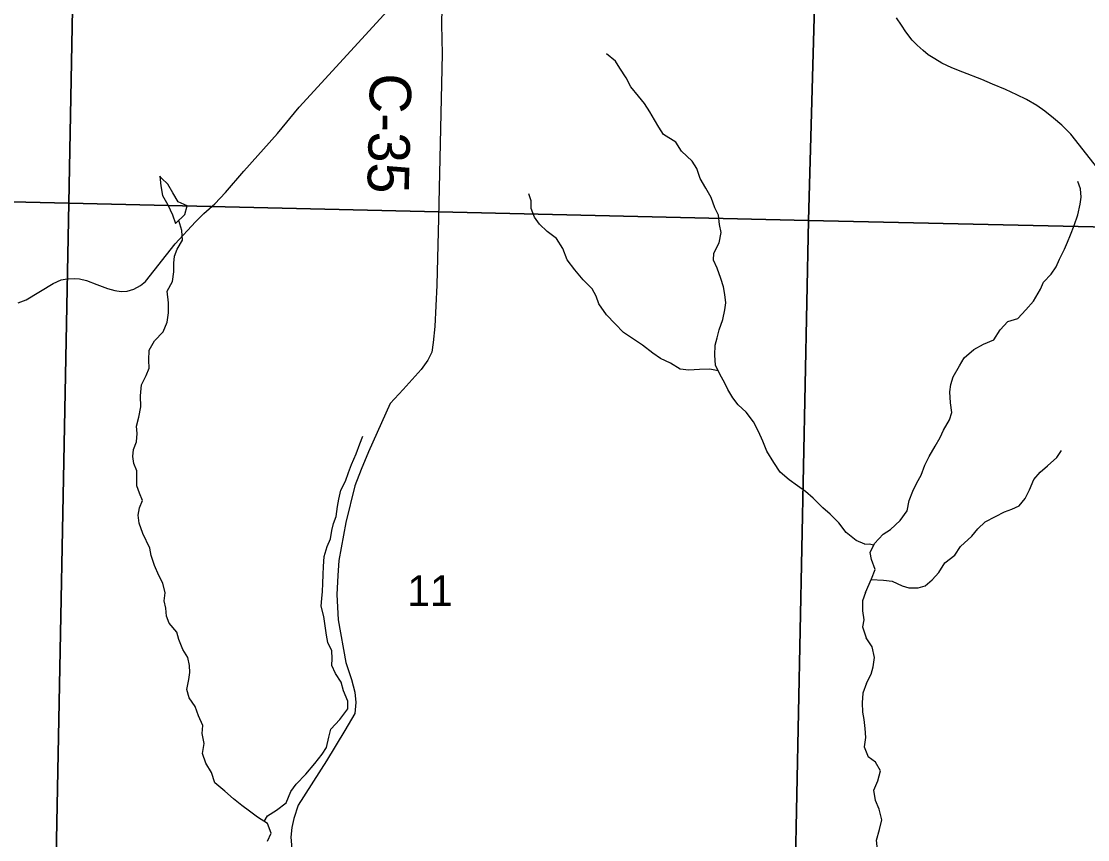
# Model space of a CAD drawing. Extents: x -3.6 to 34, y 0 to 32.8.
# Drawn here: x -1.871 to -0.41, y 27.165 to 28.286 of the extents above; entities that cross this region are included whole.
import ezdxf

# ---------------------------------------------------------------- set-up
doc = ezdxf.new("R2010")
doc.units = 0
for name, color, linetype in [('GM_X_Corporation', 7, 'Continuous'), ('GM_X_County_Road', 7, 'Continuous'), ('GM_X_County_Road_Text', 7, 'Continuous'), ('GM_X_Minor_Lake', 7, 'Continuous'), ('GM_X_Minor_River', 7, 'Continuous'), ('GM_X_Section_Text', 7, 'Continuous'), ('GM_X_State_Route', 7, 'Continuous')]:
    doc.layers.add(name, color=color, linetype=linetype)

msp = doc.modelspace()

# ---------------------------------------------------------------- linework, layer by layer
at = {"layer": 'GM_X_Corporation'}
for points in [[(-2.8121, 29.1143), (-1.8059, 29.1018), (-1.7854, 29.1006), (-1.8056, 28.0368), (-2.8264, 28.0607)], [(-1.7854, 29.1006), (-0.7893, 29.0771), (-0.7627, 29.0764), (-0.7925, 28.0131), (-1.8056, 28.0368)], [(-0.7627, 29.0764), (0.223, 29.0627), (0.2209, 28.9831), (0.2524, 28.9828), (0.2336, 27.9902), (-0.7925, 28.0131)], [(-1.8056, 28.0368), (-1.8251, 27.0226), (-2.8456, 27.0298), (-2.8264, 28.0607)], [(-0.7925, 28.0131), (-0.8131, 27.0015), (-1.8251, 27.0226), (-1.8056, 28.0368)], [(-0.7925, 28.0131), (0.2336, 27.9902), (0.2053, 26.9746), (-0.8131, 27.0015)]]:
    msp.add_lwpolyline(points, close=True, dxfattribs=at)
at = {"layer": 'GM_X_County_Road'}
msp.add_lwpolyline([(-1.2948, 28.3054), (-1.2951, 28.2819), (-1.2943, 28.2415), (-1.2993, 28.0164), (-1.3015, 27.9247), (-1.3043, 27.8681), (-1.3066, 27.8459), (-1.3084, 27.8327), (-1.3139, 27.8219), (-1.3231, 27.8089), (-1.3478, 27.7817), (-1.3654, 27.7625), (-1.395, 27.6961), (-1.4054, 27.672), (-1.4139, 27.6497), (-1.426, 27.5993), (-1.4356, 27.5472), (-1.4372, 27.5268), (-1.4386, 27.5005), (-1.4367, 27.4657), (-1.426, 27.4076), (-1.4184, 27.3841), (-1.4137, 27.3669), (-1.4125, 27.3524), (-1.4141, 27.3375), (-1.4278, 27.3143), (-1.4527, 27.2728), (-1.4914, 27.2119), (-1.4974, 27.1935), (-1.5, 27.1813), (-1.5014, 27.168), (-1.5002, 27.152)], dxfattribs=at)
at = {"layer": 'GM_X_Minor_Lake'}
for points in [[(-1.6786, 28.0714), (-1.6811, 28.0738), (-1.6798, 28.0606), (-1.6773, 28.0477), (-1.6698, 28.0346), (-1.6636, 28.021), (-1.6596, 28.009)], [(-1.6596, 28.009), (-1.6469, 28.0213), (-1.6437, 28.0335), (-1.6559, 28.0386), (-1.6633, 28.051), (-1.67, 28.063), (-1.6786, 28.0714)]]:
    msp.add_lwpolyline(points, dxfattribs=at)
at = {"layer": 'GM_X_Minor_River'}
for points in [[(-0.7155, 27.5697), (-0.7271, 27.5748), (-0.7409, 27.5856), (-0.7509, 27.5987), (-0.7629, 27.6106), (-0.7729, 27.6192), (-0.7863, 27.6326), (-0.7967, 27.6419), (-0.8074, 27.6497), (-0.8189, 27.6578), (-0.8312, 27.6682), (-0.8398, 27.6814), (-0.8495, 27.6971), (-0.855, 27.7107), (-0.8609, 27.7239), (-0.868, 27.7374), (-0.8777, 27.7505), (-0.8888, 27.7605), (-0.8962, 27.7703), (-0.9028, 27.7815), (-0.9075, 27.7913), (-0.9134, 27.8015), (-0.92, 27.815), (-0.921, 27.8286), (-0.9201, 27.8423), (-0.9176, 27.8522), (-0.9148, 27.8632), (-0.9097, 27.8777), (-0.9073, 27.8907), (-0.9059, 27.9002), (-0.9073, 27.9119), (-0.909, 27.9221), (-0.9126, 27.9338), (-0.9177, 27.9481), (-0.9228, 27.9587), (-0.9223, 27.9685), (-0.9149, 27.9827), (-0.9121, 27.9968), (-0.9142, 28.0077), (-0.9159, 28.0206), (-0.9207, 28.0304), (-0.9258, 28.0447), (-0.9332, 28.0574), (-0.9407, 28.071), (-0.9454, 28.0845), (-0.9517, 28.0947), (-0.9663, 28.1081), (-0.9741, 28.1208), (-0.9909, 28.1311), (-0.9975, 28.1413), (-1.0033, 28.151), (-1.0096, 28.1623), (-1.017, 28.1735), (-1.0255, 28.1836), (-1.0359, 28.1963), (-1.0422, 28.2087), (-1.0511, 28.2219), (-1.057, 28.2316), (-1.0692, 28.2416)], [(-0.7145, 27.5035), (-0.7062, 27.5223), (-0.7011, 27.5349), (-0.7062, 27.5485), (-0.7082, 27.5583), (-0.7023, 27.5706), (-0.6901, 27.5833), (-0.6803, 27.5899), (-0.6669, 27.6019), (-0.6572, 27.6153), (-0.6544, 27.6294), (-0.6497, 27.6424), (-0.6442, 27.6538), (-0.6383, 27.6642), (-0.6332, 27.6779), (-0.6273, 27.6898), (-0.6188, 27.7039), (-0.6122, 27.7158), (-0.6074, 27.7257), (-0.5993, 27.7399), (-0.5961, 27.7502), (-0.5978, 27.7631), (-0.5987, 27.7786), (-0.5974, 27.7885), (-0.5945, 27.7988), (-0.5857, 27.8141), (-0.5794, 27.8248), (-0.5659, 27.8364), (-0.5528, 27.8435), (-0.5385, 27.8497), (-0.53, 27.8632), (-0.5196, 27.8747), (-0.5057, 27.8787), (-0.4949, 27.8906), (-0.4844, 27.9026), (-0.4749, 27.919), (-0.4708, 27.9289), (-0.46, 27.9397), (-0.4534, 27.9497), (-0.4486, 27.9604), (-0.442, 27.9738), (-0.4376, 27.9837), (-0.4336, 27.9936), (-0.4285, 28.0062), (-0.4238, 28.0211), (-0.4202, 28.0356), (-0.4189, 28.0451), (-0.4198, 28.0568), (-0.4237, 28.0666)], [(-0.9163, 27.8074), (-0.9275, 27.8096), (-0.9419, 27.8089), (-0.9566, 27.8083), (-0.9684, 27.8096), (-0.9814, 27.8177), (-0.9951, 27.8243), (-1.0055, 27.8314), (-1.0197, 27.8425), (-1.0457, 27.8595), (-1.0572, 27.8714), (-1.0692, 27.8841), (-1.0797, 27.8991), (-1.0833, 27.9093), (-1.0887, 27.9194), (-1.1011, 27.9321), (-1.1126, 27.9456), (-1.1231, 27.9594), (-1.129, 27.9748), (-1.1376, 27.9884), (-1.1506, 27.998), (-1.161, 28.008), (-1.1676, 28.0178), (-1.1724, 28.0298), (-1.1722, 28.0401), (-1.1757, 28.0499)], [(-1.677, 27.5161), (-1.6824, 27.5266), (-1.6883, 27.5405), (-1.6927, 27.5541), (-1.6948, 27.5639), (-1.7042, 27.5842), (-1.7094, 27.5986), (-1.7107, 27.6092), (-1.709, 27.6194), (-1.7046, 27.6294), (-1.7089, 27.6395), (-1.7125, 27.6497), (-1.7123, 27.6603), (-1.7125, 27.6702), (-1.7164, 27.68), (-1.7181, 27.6898), (-1.7171, 27.6993), (-1.7128, 27.71), (-1.7118, 27.7214), (-1.7128, 27.7313), (-1.7099, 27.7438), (-1.7072, 27.7579), (-1.7074, 27.7727), (-1.7062, 27.7879), (-1.6996, 27.8009), (-1.6956, 27.8108), (-1.6961, 27.8218), (-1.6956, 27.8355), (-1.6882, 27.8481), (-1.6764, 27.8608), (-1.6709, 27.8738), (-1.6692, 27.8867), (-1.6691, 27.9004), (-1.6709, 27.9163), (-1.6635, 27.9297), (-1.6618, 27.943), (-1.6617, 27.9547), (-1.6607, 27.9642), (-1.6571, 27.9738), (-1.6497, 27.9864), (-1.6507, 27.9997), (-1.6551, 28.0133)], [(-1.5379, 27.1895), (-1.5335, 27.1972), (-1.5211, 27.205), (-1.508, 27.2151), (-1.5015, 27.2304), (-1.4944, 27.2407), (-1.481, 27.2542), (-1.4688, 27.2692), (-1.4588, 27.2816), (-1.4525, 27.2911), (-1.4497, 27.3049), (-1.4469, 27.3159), (-1.4346, 27.3294), (-1.4235, 27.344), (-1.4233, 27.3546), (-1.4292, 27.3686), (-1.4324, 27.3806), (-1.4402, 27.3923), (-1.4453, 27.4032), (-1.4451, 27.4131), (-1.4456, 27.4233), (-1.4507, 27.435), (-1.4528, 27.4448), (-1.4563, 27.4705), (-1.4599, 27.4845), (-1.4589, 27.4951), (-1.458, 27.5046), (-1.4578, 27.5156), (-1.4572, 27.5278), (-1.4567, 27.5388), (-1.4557, 27.5525), (-1.4518, 27.5666), (-1.4471, 27.5769), (-1.4454, 27.5883), (-1.4429, 27.5978), (-1.4393, 27.6074), (-1.4376, 27.6214), (-1.4359, 27.6313), (-1.4331, 27.6435), (-1.4268, 27.6561), (-1.4225, 27.668), (-1.4185, 27.679), (-1.4119, 27.6936), (-1.4069, 27.7073), (-1.4029, 27.7176)], [(-0.7066, 27.5213), (-0.6899, 27.5203), (-0.6777, 27.519), (-0.6644, 27.5127), (-0.6549, 27.5098), (-0.6424, 27.5096), (-0.6326, 27.5124), (-0.6229, 27.5205), (-0.614, 27.5309), (-0.6058, 27.544), (-0.592, 27.5544), (-0.5842, 27.5663), (-0.5689, 27.5806), (-0.5604, 27.5906), (-0.5503, 27.6002), (-0.5364, 27.6073), (-0.524, 27.6139), (-0.5142, 27.6175), (-0.5041, 27.6222), (-0.4959, 27.6322), (-0.49, 27.644), (-0.4838, 27.6582), (-0.4753, 27.6685), (-0.4652, 27.6771), (-0.4525, 27.6883), (-0.4458, 27.6978)], [(-0.7155, 27.5697), (-0.7094, 27.57), (-0.7032, 27.5689)], [(-1.5333, 27.1623), (-1.5285, 27.1734), (-1.5333, 27.1866), (-1.5471, 27.1954), (-1.5582, 27.2036), (-1.5685, 27.2114), (-1.58, 27.2207), (-1.5919, 27.2311), (-1.6058, 27.2426), (-1.6102, 27.2566), (-1.6179, 27.2693), (-1.6227, 27.2825), (-1.6203, 27.2962), (-1.6228, 27.3099), (-1.6222, 27.3212), (-1.6281, 27.3344), (-1.6325, 27.3472), (-1.641, 27.3592), (-1.6439, 27.3702), (-1.6411, 27.3843), (-1.6401, 27.3938), (-1.6402, 27.4033), (-1.6427, 27.4142), (-1.6493, 27.4251), (-1.6548, 27.4391), (-1.6577, 27.4489), (-1.6681, 27.4612), (-1.6717, 27.471), (-1.6726, 27.482), (-1.675, 27.4918), (-1.6737, 27.5028), (-1.677, 27.5161)], [(-0.7145, 27.5035), (-0.7185, 27.4919), (-0.7183, 27.4782), (-0.7169, 27.4657), (-0.7183, 27.4562), (-0.7136, 27.4411)], [(-0.7132, 27.3789), (-0.7067, 27.3912), (-0.7041, 27.4016), (-0.7019, 27.4142), (-0.7051, 27.429), (-0.7136, 27.4411)], [(-0.7132, 27.3789), (-0.7179, 27.3652), (-0.7188, 27.3523), (-0.7186, 27.3394), (-0.7169, 27.3295), (-0.7152, 27.317), (-0.7146, 27.3045), (-0.7163, 27.292), (-0.7109, 27.2783)], [(-0.7085, 27.0754), (-0.7029, 27.0868), (-0.6995, 27.0953), (-0.6985, 27.1055), (-0.6953, 27.1154), (-0.692, 27.1273), (-0.6933, 27.1394), (-0.6981, 27.1507), (-0.6994, 27.164), (-0.6951, 27.1785), (-0.6922, 27.1918), (-0.6955, 27.2066), (-0.7006, 27.2183), (-0.703, 27.2323), (-0.6975, 27.2453), (-0.694, 27.259), (-0.7009, 27.2709), (-0.7109, 27.2783)]]:
    msp.add_lwpolyline(points, dxfattribs=at)
at = {"layer": 'GM_X_State_Route'}
for points in [[(-1.875, 27.9004), (-1.8641, 27.9046), (-1.8271, 27.9271), (-1.8161, 27.9317), (-1.8077, 27.9334), (-1.7983, 27.9339), (-1.7909, 27.9332), (-1.7812, 27.9308), (-1.7671, 27.9254), (-1.7528, 27.9201), (-1.7426, 27.9173), (-1.734, 27.9158), (-1.7256, 27.9163), (-1.7165, 27.9189), (-1.7076, 27.924), (-1.7007, 27.9298), (-1.6599, 27.9814), (-1.6322, 28.0115), (-1.6209, 28.023), (-1.6057, 28.036), (-1.591, 28.0516), (-1.5659, 28.0808), (-1.5198, 28.1327), (-1.4901, 28.1685), (-1.3693, 28.3004)], [(-0.3962, 28.0843), (-0.4332, 28.1316), (-0.4454, 28.1438), (-0.4567, 28.1537), (-0.4689, 28.1631), (-0.4799, 28.1707), (-0.4941, 28.1792), (-0.507, 28.1856), (-0.5228, 28.1926), (-0.5405, 28.2003), (-0.5552, 28.2063), (-0.5813, 28.2166), (-0.5963, 28.2223), (-0.6098, 28.2291), (-0.6195, 28.2348), (-0.6284, 28.2403), (-0.6355, 28.2462), (-0.6435, 28.2534), (-0.6505, 28.2603), (-0.6591, 28.2716), (-0.6652, 28.2808), (-0.6719, 28.2911)]]:
    msp.add_lwpolyline(points, dxfattribs=at)

# ---------------------------------------------------------------- texts
at = {"layer": 'GM_X_County_Road_Text'}
msp.add_text('C-35', height=0.05682, rotation=268.6273, dxfattribs=at).set_placement((-1.3929, 28.2155))
at = {"layer": 'GM_X_Section_Text'}
msp.add_text('11', height=0.04186, rotation=0, dxfattribs=at).set_placement((-1.3421, 27.4849))

doc.saveas('drawing.dxf')
